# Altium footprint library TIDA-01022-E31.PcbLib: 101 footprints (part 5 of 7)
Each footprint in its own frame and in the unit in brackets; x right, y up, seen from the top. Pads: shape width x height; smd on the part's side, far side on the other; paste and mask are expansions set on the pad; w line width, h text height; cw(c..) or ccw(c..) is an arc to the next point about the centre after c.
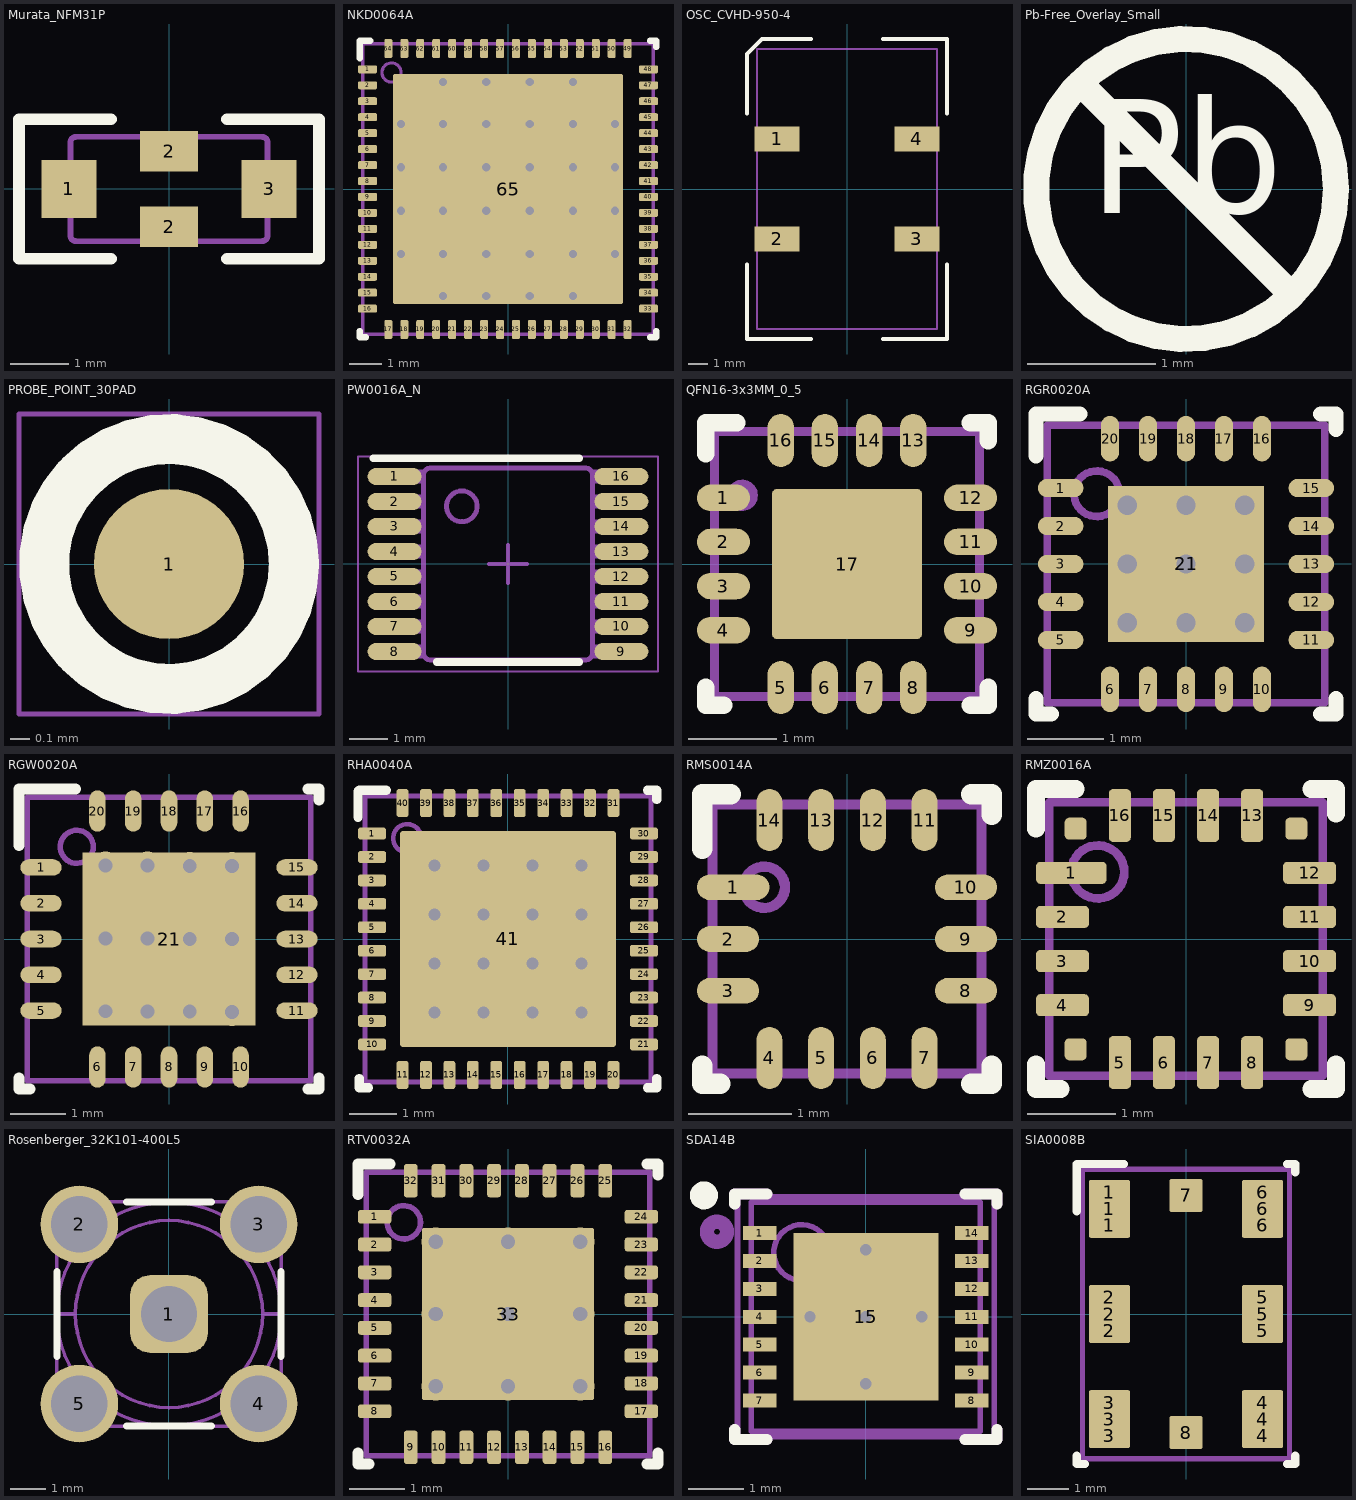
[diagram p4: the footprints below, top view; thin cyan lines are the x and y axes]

## Murata_NFM31P [mm] "SMD, 3-Leads, Body 3.2x1.6mm"
height 1.5
pads (4):
  rect 0.95x1 smd paste-2 mask-2: 1(-1.725,0) 3(1.725,0)
  rect 1x0.7 smd paste-2 mask+0: 2(0,-0.65) 2(0,0.65)
Top Overlay:
  lines w0.2: -1,-1.2 -2.586,-1.2 -2.586,1.2 -1,1.2 ; 1,-1.2 2.586,-1.2 2.586,1.2 1,1.2
Top Paste:
  rectangle: -0.5,0.3 0.5,1.3
  region: 0.5,-0.3 -0.5,-0.3 -0.5,-1.3 0.5,-1.3
  rectangle: 1.251,-0.6 2.201,0.6
  region: -1.251,0.6 -2.201,0.6 -2.201,-0.6 -1.251,-0.6
Top Solder:
  region: -0.7,1 -2.2,1 -2.2,-1 -0.7,-1
  rectangle: 0.7,-1 2.2,1
Mechanical 5:
  lines w0.1: -1.7,-0.8 ccw(c-1.6,-0.8) -1.6,-0.9 1.6,-0.9 ccw(c1.6,-0.8) 1.7,-0.8 1.7,0.8 ccw(c1.6,0.8) 1.6,0.9 -1.6,0.9 ccw(c-1.6,0.8) -1.7,0.8 -1.7,-0.8
  text ".Designator" at -0.117,-0.322 h0.51
3D body "NFM31PC276B0J3L.stp": height 1.5, standoff 0, extent -1.7,-0.9 1.7,0.9

## NKD0064A [mm] "QFN, 64-Leads, Body 9x9mm, Pitch 0.5mm"
height 0.8
pads (65):
  rrect40% 0.6x0.25 smd: 1(-4.4,3.75) 2(-4.4,3.25) 3(-4.4,2.75) 4(-4.4,2.25) 5(-4.4,1.75) 6(-4.4,1.25) 7(-4.4,0.75) 8(-4.4,0.25) 9(-4.4,-0.25) 10(-4.4,-0.75) 11(-4.4,-1.25) 12(-4.4,-1.75) 13(-4.4,-2.25) 14(-4.4,-2.75) 15(-4.4,-3.25) 16(-4.4,-3.75) 33(4.4,-3.75) 34(4.4,-3.25) 35(4.4,-2.75) 36(4.4,-2.25) 37(4.4,-1.75) 38(4.4,-1.25) 39(4.4,-0.75) 40(4.4,-0.25) 41(4.4,0.25) 42(4.4,0.75) 43(4.4,1.25) 44(4.4,1.75) 45(4.4,2.25) 46(4.4,2.75) 47(4.4,3.25) 48(4.4,3.75)
  rrect40% 0.25x0.6 smd: 17(-3.75,-4.4) 18(-3.25,-4.4) 19(-2.75,-4.4) 20(-2.25,-4.4) 21(-1.75,-4.4) 22(-1.25,-4.4) 23(-0.75,-4.4) 24(-0.25,-4.4) 25(0.25,-4.4) 26(0.75,-4.4) 27(1.25,-4.4) 28(1.75,-4.4) 29(2.25,-4.4) 30(2.75,-4.4) 31(3.25,-4.4) 32(3.75,-4.4) 49(3.75,4.4) 50(3.25,4.4) 51(2.75,4.4) 52(2.25,4.4) 53(1.75,4.4) 54(1.25,4.4) 55(0.75,4.4) 56(0.25,4.4) 57(-0.25,4.4) 58(-0.75,4.4) 59(-1.25,4.4) 60(-1.75,4.4) 61(-2.25,4.4) 62(-2.75,4.4) 63(-3.25,4.4) 64(-3.75,4.4)
  rrect1% 7.2x7.2 smd paste-3.6: 65(0,0)
via 0.68,0.68 diameter 0.508 hole 0.254
via -0.68,0.68 diameter 0.508 hole 0.254
via -0.68,-0.68 diameter 0.508 hole 0.254
via 0.68,-0.68 diameter 0.508 hole 0.254
via -2.04,0.68 diameter 0.508 hole 0.254
via 2.04,0.68 diameter 0.508 hole 0.254
via 2.04,-0.68 diameter 0.508 hole 0.254
via -2.04,-0.68 diameter 0.508 hole 0.254
via -2.04,-2.04 diameter 0.508 hole 0.254
via -0.68,-2.04 diameter 0.508 hole 0.254
via 0.68,-2.04 diameter 0.508 hole 0.254
via 2.04,-2.04 diameter 0.508 hole 0.254
via -2.04,2.04 diameter 0.508 hole 0.254
via -0.68,2.04 diameter 0.508 hole 0.254
via 0.68,2.04 diameter 0.508 hole 0.254
via 2.04,2.04 diameter 0.508 hole 0.254
via -2.04,3.35 diameter 0.508 hole 0.254
via -0.68,3.35 diameter 0.508 hole 0.254
via 0.68,3.35 diameter 0.508 hole 0.254
via 2.04,3.35 diameter 0.508 hole 0.254
via 0.68,-3.35 diameter 0.508 hole 0.254
via 2.04,-3.35 diameter 0.508 hole 0.254
via -0.68,-3.35 diameter 0.508 hole 0.254
via -2.04,-3.35 diameter 0.508 hole 0.254
via 3.35,-0.68 diameter 0.508 hole 0.254
via 3.35,-2.04 diameter 0.508 hole 0.254
via -3.35,-2.04 diameter 0.508 hole 0.254
via -3.35,-0.68 diameter 0.508 hole 0.254
via -3.35,2.04 diameter 0.508 hole 0.254
via -3.35,0.68 diameter 0.508 hole 0.254
via 3.35,2.04 diameter 0.508 hole 0.254
via 3.35,0.68 diameter 0.508 hole 0.254
Top Overlay:
  lines w0.2: -4.65,-4.45 -4.65,-4.65 -4.45,-4.65 ; -4.65,4.1 -4.65,4.65 -4.32,4.65 ; 4.45,-4.65 4.65,-4.65 4.65,-4.45 ; 4.45,4.65 4.65,4.65 4.65,4.45
Top Paste:
  rectangle: -0.58,-0.58 0.58,0.58
  rectangle: 0.78,-0.58 1.94,0.58
  rectangle: 2.14,-0.58 3.3,0.58
  rectangle: 0.78,0.78 1.94,1.94
  rectangle: 0.78,2.14 1.94,3.3
  rectangle: 2.14,2.14 3.3,3.3
  rectangle: 2.14,0.78 3.3,1.94
  rectangle: -0.58,0.78 0.58,1.94
  rectangle: -0.58,2.14 0.58,3.3
  rectangle: -1.94,2.14 -0.78,3.3
  rectangle: -3.3,2.14 -2.14,3.3
  rectangle: -3.3,0.78 -2.14,1.94
  rectangle: -1.94,0.78 -0.78,1.94
  rectangle: -1.94,-0.58 -0.78,0.58
  rectangle: -3.3,-0.58 -2.14,0.58
  rectangle: -3.3,-1.94 -2.14,-0.78
  rectangle: -1.94,-1.94 -0.78,-0.78
  rectangle: -0.58,-1.94 0.58,-0.78
  rectangle: 0.78,-1.94 1.94,-0.78
  rectangle: 2.14,-1.94 3.3,-0.78
  rectangle: 2.14,-3.3 3.3,-2.14
  rectangle: 0.78,-3.3 1.94,-2.14
  rectangle: -0.58,-3.3 0.58,-2.14
  rectangle: -1.94,-3.3 -0.78,-2.14
  rectangle: -3.3,-3.3 -2.14,-2.14
Mechanical 5:
  circle w0.1: c-3.65,3.65 r0.3
  lines w0.1: -4.55,-4.55 -4.55,4.55 4.55,4.55 4.55,-4.55 -4.55,-4.55
  text ".Designator" at -0.047,0.001 h0.51
3D body: height 0.8, standoff 0, extent -4.549,-4.549 4.549,4.549
3D body: height 0.81, standoff 0.5, extent -3.949,3.351 -3.351,3.949

## OSC_CVHD-950-4 [mil] "Crystek recommended land pattern 2011-02-22 Rev H"
height 210
pads (4):
  rect 90x50 smd: 1(-140,100) 2(-140,-100) 3(140,-100) 4(140,100)
Top Overlay:
  lines w7.87: -200,-151.18 -200,-300 -71.73,-300 ; -200,151.18 -200,270 -170,300 -71.73,300 ; 71.73,-300 200,-300 200,-151.18 ; 71.73,300 200,300 200,151.18
Mechanical 5:
  lines w4: -180,-280 180,-280 180,280 -180,280 -180,-280
  text ".Designator" at 18.56,-12.02 h20
3D body "Crystek_CVHD-950.stp": height 209.06, standoff -0.39, extent -179.84,-279.53 180,279.53

## Pb-Free_Overlay_Small [mm]
height 9.53
Top Overlay:
  circle w0.203: c0,0 r1.168
  lines w0.203: -0.826,0.826 0.826,-0.826
  text "Pb" at -0.752,-0.48 h1.52

## PROBE_POINT_30PAD [mil]
height 59.06
pads (1):
  round 30 smd: 1(0,0)
Top Overlay:
  circle w10: c0,0 r25
Mechanical 16:
  circle w1: c0,0 r25
  circle w1: c0,0 r29.15
  lines w1: -30,-30 30,-30 30,30 -30,30 -30,-30
Mechanical 30:
  text "1" at -10,-10 h25
Mechanical 31:
  text ".Designator" at -179.07,-26.87 h50

## PW0016A_N [mm] "TSOP, 16-Leads, Body 5x4.4mm, Pitch 0.65mm, IPC Medium Density"
height 1.2
pads (16):
  oval 1.4x0.45 smd: 1(-2.95,2.275) 2(-2.95,1.625) 3(-2.95,0.975) 4(-2.95,0.325) 5(-2.95,-0.325) 6(-2.95,-0.975) 7(-2.95,-1.625) 8(-2.95,-2.275) 9(2.95,-2.275) 10(2.95,-1.625) 11(2.95,-0.975) 12(2.95,-0.325) 13(2.95,0.325) 14(2.95,0.975) 15(2.95,1.625) 16(2.95,2.275)
Top Overlay:
  lines w0.2: -3.5,2.75 1.85,2.75 ; -1.85,-2.55 1.85,-2.55
Mechanical 5:
  drawing of 202 lines, arcs and shapes, not listed
  text ".Designator" at 0.859,0.328 h0.51
Mechanical 15:
  lines w0.05: -3.9,-2.8 -3.9,2.8 3.9,2.8 3.9,-2.8 -3.9,-2.8
  lines w0.1: -0.5,0 0.5,0 ; 0,-0.5 0,0.5
3D body "PW0016A.stp": height 1, standoff 0, extent -3.21,-2.5 3.21,2.5

## QFN16-3x3MM_0_5 [mm] "QFN, 16-Leads, Body 3x3mm, Pitch 0.5mm"
height 1
pads (17):
  rrect100% 0.6x0.3 smd: 1(-1.4,0.75) 2(-1.4,0.25) 3(-1.4,-0.25) 4(-1.4,-0.75) 9(1.4,-0.75) 10(1.4,-0.25) 11(1.4,0.25) 12(1.4,0.75)
  rrect100% 0.3x0.6 smd: 5(-0.75,-1.4) 6(-0.25,-1.4) 7(0.25,-1.4) 8(0.75,-1.4) 13(0.75,1.4) 14(0.25,1.4) 15(-0.25,1.4) 16(-0.75,1.4)
  rrect6% 1.7x1.7 smd paste-2: 17(0,0)
Top Overlay:
  lines w0.2: -1.6,-1.4 -1.6,-1.6 -1.4,-1.6 ; -1.6,1.25 -1.6,1.6 -1.25,1.6 ; 1.4,-1.6 1.6,-1.6 1.6,-1.4 ; 1.4,1.6 1.6,1.6 1.6,1.4
Top Paste:
  rectangle: -0.775,-0.774 0.774,0.775
Mechanical 5:
  circle w0.1: c-1.187,0.779 r0.127
  lines w0.1: -1.5,-1.5 1.5,-1.5 1.5,1.5 -1.5,1.5 -1.5,-1.5
3D body: height 1, standoff 0, extent -1.5,-1.5 1.5,1.5
3D body: height 1.01, standoff 1, extent -1.099,0.501 -0.501,1.099

## RGR0020A [mm] "QFN, 20-Leads, Body 3.5x3.5mm, Pitch 0.5mm, Thermal Pad 2.05x2.05mm, TI Recommended"
height 1
pads (21):
  oval 0.6x0.24 smd: 1(-1.65,1) 2(-1.65,0.5) 3(-1.65,0) 4(-1.65,-0.5) 5(-1.65,-1) 11(1.65,-1) 12(1.65,-0.5) 13(1.65,0) 14(1.65,0.5) 15(1.65,1)
  oval 0.24x0.6 smd: 6(-1,-1.65) 7(-0.5,-1.65) 8(0,-1.65) 9(0.5,-1.65) 10(1,-1.65) 16(1,1.65) 17(0.5,1.65) 18(0,1.65) 19(-0.5,1.65) 20(-1,1.65)
  rect 2.05x2.05 smd paste-1.025: 21(0,0)
via 0.775,0 diameter 0.508 hole 0.254
via -0.775,0 diameter 0.508 hole 0.254
via 0,0.775 diameter 0.508 hole 0.254
via 0,-0.775 diameter 0.508 hole 0.254
via 0,0 diameter 0.508 hole 0.254
via 0.775,0.775 diameter 0.508 hole 0.254
via 0.775,-0.775 diameter 0.508 hole 0.254
via -0.775,-0.775 diameter 0.508 hole 0.254
via -0.775,0.775 diameter 0.508 hole 0.254
Top Overlay:
  lines w0.2: -1.975,-1.775 -1.975,-1.975 -1.775,-1.975 ; -1.975,1.425 -1.975,1.975 -1.4,1.975 ; 1.775,-1.975 1.975,-1.975 1.975,-1.775 ; 1.775,1.975 1.975,1.975 1.975,1.775
Top Paste:
  rectangle: 0.099,-1.017 1.016,-0.1
  region: -0.099,-0.1 -1.016,-0.1 -1.016,-1.017 -0.099,-1.017
  region: -0.099,1.017 -1.016,1.017 -1.016,0.1 -0.099,0.1
  rectangle: 0.101,0.1 1.018,1.017
Mechanical 5:
  circle w0.1: c-1.175,0.925 r0.3
  lines w0.1: -1.825,-1.825 1.825,-1.825 1.825,1.825 -1.825,1.825 -1.825,-1.825
  text ".Designator" at -0.052,0.631 h0.51
3D body: height 1, standoff 0, extent -1.825,-1.825 1.825,1.825
3D body: height 1.01, standoff 0.5, extent -1.474,0.626 -0.876,1.224

## RGW0020A [mm] "QFN, 20-Leads, Body 5x5mm, Pitch 0.65mm, Thermal Pad 3.15x3.15mm, TI Recommended"
height 1
pads (21):
  oval 0.75x0.3 smd: 1(-2.325,1.3) 2(-2.325,0.65) 3(-2.325,0) 4(-2.325,-0.65) 5(-2.325,-1.3) 11(2.325,-1.3) 12(2.325,-0.65) 13(2.325,0) 14(2.325,0.65) 15(2.325,1.3)
  oval 0.3x0.75 smd: 6(-1.3,-2.325) 7(-0.65,-2.325) 8(0,-2.325) 9(0.65,-2.325) 10(1.3,-2.325) 16(1.3,2.325) 17(0.65,2.325) 18(0,2.325) 19(-0.65,2.325) 20(-1.3,2.325)
  rect 3.15x3.15 smd paste-1.575: 21(0,0)
via -0.389,-1.317 diameter 0.508 hole 0.254
via -0.389,0.008 diameter 0.508 hole 0.254
via -1.156,0.013 diameter 0.508 hole 0.254
via -0.389,1.333 diameter 0.508 hole 0.254
via -1.156,1.338 diameter 0.508 hole 0.254
via -1.156,-1.312 diameter 0.508 hole 0.254
via 0.377,1.329 diameter 0.508 hole 0.254
via 0.377,0.004 diameter 0.508 hole 0.254
via 0.377,-1.321 diameter 0.508 hole 0.254
via 1.143,1.325 diameter 0.508 hole 0.254
via 1.143,0 diameter 0.508 hole 0.254
via 1.143,-1.325 diameter 0.508 hole 0.254
Top Overlay:
  lines w0.2: -2.725,-2.525 -2.725,-2.725 -2.525,-2.725 ; -2.725,1.7 -2.725,2.725 -1.7,2.725 ; 2.525,-2.725 2.725,-2.725 2.725,-2.525 ; 2.525,2.725 2.725,2.725 2.725,2.525
Top Paste:
  rectangle: 0.1,-1.468 1.468,-0.1
  region: -0.1,-0.1 -1.468,-0.1 -1.468,-1.468 -0.1,-1.468
  region: -0.1,1.468 -1.468,1.468 -1.468,0.1 -0.1,0.1
  rectangle: 0.1,0.1 1.468,1.468
Mechanical 5:
  circle w0.1: c-1.675,1.675 r0.3
  lines w0.1: -2.575,-2.575 2.575,-2.575 2.575,2.575 -2.575,2.575 -2.575,-2.575
  text ".Designator" at -0.658,-0.13 h0.51
3D body: height 1.01, standoff 0.5, extent -1.974,1.376 -1.376,1.974
3D body: height 1, standoff 0, extent -2.575,-2.575 2.575,2.575

## RHA0040A [mm] "QFN, 40-Leads, Body 6x6mm, Pitch 0.5mm, Thermal Pad 4.6x4.6mm, TI Recommended"
height 1
pads (41):
  rrect40% 0.6x0.25 smd: 1(-2.9,2.25) 2(-2.9,1.75) 3(-2.9,1.25) 4(-2.9,0.75) 5(-2.9,0.25) 6(-2.9,-0.25) 7(-2.9,-0.75) 8(-2.9,-1.25) 9(-2.9,-1.75) 10(-2.9,-2.25) 21(2.9,-2.25) 22(2.9,-1.75) 23(2.9,-1.25) 24(2.9,-0.75) 25(2.9,-0.25) 26(2.9,0.25) 27(2.9,0.75) 28(2.9,1.25) 29(2.9,1.75) 30(2.9,2.25)
  rrect40% 0.25x0.6 smd: 11(-2.25,-2.9) 12(-1.75,-2.9) 13(-1.25,-2.9) 14(-0.75,-2.9) 15(-0.25,-2.9) 16(0.25,-2.9) 17(0.75,-2.9) 18(1.25,-2.9) 19(1.75,-2.9) 20(2.25,-2.9) 31(2.25,2.9) 32(1.75,2.9) 33(1.25,2.9) 34(0.75,2.9) 35(0.25,2.9) 36(-0.25,2.9) 37(-0.75,2.9) 38(-1.25,2.9) 39(-1.75,2.9) 40(-2.25,2.9)
  rrect2% 4.6x4.6 smd paste-2.3: 41(0,0)
via 1.57,-1.57 diameter 0.508 hole 0.254
via 1.57,-0.523 diameter 0.508 hole 0.254
via 1.57,1.57 diameter 0.508 hole 0.254
via 1.57,0.523 diameter 0.508 hole 0.254
via -1.57,-1.57 diameter 0.508 hole 0.254
via -1.57,-0.523 diameter 0.508 hole 0.254
via -1.57,1.57 diameter 0.508 hole 0.254
via -1.57,0.523 diameter 0.508 hole 0.254
via -0.523,0.523 diameter 0.508 hole 0.254
via 0.523,-1.57 diameter 0.508 hole 0.254
via 0.523,0.523 diameter 0.508 hole 0.254
via 0.523,1.57 diameter 0.508 hole 0.254
via -0.523,1.57 diameter 0.508 hole 0.254
via -0.523,-0.523 diameter 0.508 hole 0.254
via -0.523,-1.57 diameter 0.508 hole 0.254
via 0.523,-0.523 diameter 0.508 hole 0.254
Top Overlay:
  lines w0.2: -3.2,2.6 -3.2,3.15 ; -3.175,-2.975 -3.175,-3.175 -2.975,-3.175 ; -3.175,3.175 -2.6,3.175 ; 2.975,-3.175 3.175,-3.175 3.175,-2.975 ; 2.975,3.175 3.175,3.175 3.175,2.975
Top Paste:
  region: -0.84,-0.84 -2.12,-0.84 -2.12,-2.12 -0.84,-2.12
  rectangle: 0.84,-2.12 2.12,-0.84
  rectangle: -0.64,-2.12 0.64,-0.84
  rectangle: -0.64,0.84 0.64,2.12
  rectangle: 0.84,0.84 2.12,2.12
  region: -0.84,2.12 -2.12,2.12 -2.12,0.84 -0.84,0.84
  region: -0.84,0.64 -2.12,0.64 -2.12,-0.64 -0.84,-0.64
  rectangle: 0.84,-0.64 2.12,0.64
  rectangle: -0.64,-0.64 0.64,0.64
Mechanical 5:
  circle w0.1: c-2.15,2.15 r0.3
  lines w0.1: -3.05,-3.05 -3.05,3.05 3.05,3.05 3.05,-3.05 -3.05,-3.05
  text ".Designator" at 0.457,-0.576 h0.51
3D body "RHA0040A.stp": height 1, standoff 0, extent -3,-3 3,3

## RMS0014A [mm] "QFN, Body 2.6x2.6mm, Pitch 0.5mm"
height 0.6
pads (14):
  oval 0.7x0.25 smd: 1(-1.1,0.5)
  oval 0.6x0.25 smd: 2(-1.15,0) 3(-1.15,-0.5) 8(1.15,-0.5) 9(1.15,0) 10(1.15,0.5)
  oval 0.25x0.6 smd: 4(-0.75,-1.15) 5(-0.25,-1.15) 6(0.25,-1.15) 7(0.75,-1.15) 11(0.75,1.15) 12(0.25,1.15) 13(-0.25,1.15) 14(-0.75,1.15)
Top Overlay:
  lines w0.2: -1.4,-1.225 -1.4,-1.4 -1.225,-1.4 ; -1.4,0.875 -1.4,1.4 -1.125,1.4 ; 1.2,-1.4 1.4,-1.4 1.4,-1.225 ; 1.2,1.4 1.4,1.4 1.4,1.2
Mechanical 5:
  circle w0.1: c-0.8,0.5 r0.2
  lines w0.1: -1.3,-1.3 1.3,-1.3 1.3,1.3 -1.3,1.3 -1.3,-1.3
  text ".Designator" at 0.51,-0.374 h0.51
3D body: height 0.6, standoff 0, extent -1.299,-1.299 1.299,1.299
3D body: height 0.61, standoff 0, extent -0.999,0.301 -0.601,0.699

## RMZ0016A [mm] "QFN, 16-Leads, Body 3.0x3.0 mm, Pitch 0.5mm"
height 0.65
pads (20):
  rrect40% 0.8x0.25 smd paste+0 mask+0.07: 1(-1.3,0.75)
  rrect40% 0.6x0.25 smd paste+0 mask+0.07: 2(-1.4,0.25) 3(-1.4,-0.25) 4(-1.4,-0.75) 9(1.4,-0.75) 10(1.4,-0.25) 11(1.4,0.25) 12(1.4,0.75)
  rrect40% 0.25x0.6 smd paste+0 mask+0.07: 5(-0.75,-1.4) 6(-0.25,-1.4) 7(0.25,-1.4) 8(0.75,-1.4) 13(0.75,1.4) 14(0.25,1.4) 15(-0.25,1.4) 16(-0.75,1.4)
  rrect40% 0.25x0.25 smd paste+0 mask+0.07: ""(-1.25,-1.25) ""(-1.25,1.25) ""(1.25,-1.25) ""(1.25,1.25)
Top Overlay:
  lines w0.2: -1.7,-1.42 -1.7,-1.7 -1.42,-1.7 ; -1.7,1.25 -1.7,1.7 -1.25,1.7 ; 1.42,-1.7 1.7,-1.7 1.7,-1.42 ; 1.42,1.7 1.7,1.7 1.7,1.42
Mechanical 5:
  circle w0.1: c-1,0.76 r0.3
  lines w0.1: -1.55,-1.55 1.55,-1.55 1.55,1.55 -1.55,1.55 -1.55,-1.55
  text ".Designator" at -0.302,-0.491 h0.51
3D body: height 0.65, standoff 0, extent -1.55,-1.55 1.55,1.55
3D body: height 0.66, standoff 0.5, extent -1.299,0.461 -0.701,1.059

## Rosenberger_32K101-400L5 [mm] "SMA, 50 Ohm, TH"
height 9.5
pads (5):
  rrect50% 2.2x2.2 hole 1.6: 1(0,0)
  round 2.2 hole 1.6: 2(-2.54,2.54) 3(2.54,2.54) 4(2.54,-2.54) 5(-2.54,-2.54)
Top Overlay:
  lines w0.2: -3.175,-1.2 -3.175,1.2 ; -1.2,-3.175 1.2,-3.175 ; -1.2,3.175 1.2,3.175 ; 3.175,-1.2 3.175,1.2
Mechanical 5:
  lines w0.1: -3.175,0 ccw(c0,0) 3.175,0 ; -3.175,0 cw(c0,0) 3.175,0 ; -3.175,0 -2.65,0 ; -2.65,0 ccw(c0,0) 2.65,0 ; -2.65,0 cw(c0,0) 2.65,0 ; 2.65,0 3.175,0 ; -3.175,-2.825 ccw(c0,0) -2.825,-3.175 2.825,-3.175 ccw(c0,0) 3.175,-2.825 3.175,2.825 ccw(c0,0) 2.825,3.175 -2.825,3.175 ccw(c0,0) -3.175,2.825 -3.175,-2.825
  text ".Designator" at 0.221,-0.611 h0.51
3D body "32k101-400l5.stp": height 9.51, standoff -3.99, extent -3.175,-3.175 3.175,3.175

## RTV0032A [mm] "QFN, 32-Leads, Body 5x5mm, Pitch 0.5mm"
height 0.8
pads (33):
  rrect40% 0.6x0.25 smd: 1(-2.4,1.75) 2(-2.4,1.25) 3(-2.4,0.75) 4(-2.4,0.25) 5(-2.4,-0.25) 6(-2.4,-0.75) 7(-2.4,-1.25) 8(-2.4,-1.75) 17(2.4,-1.75) 18(2.4,-1.25) 19(2.4,-0.75) 20(2.4,-0.25) 21(2.4,0.25) 22(2.4,0.75) 23(2.4,1.25) 24(2.4,1.75)
  rrect40% 0.25x0.6 smd: 9(-1.75,-2.4) 10(-1.25,-2.4) 11(-0.75,-2.4) 12(-0.25,-2.4) 13(0.25,-2.4) 14(0.75,-2.4) 15(1.25,-2.4) 16(1.75,-2.4) 25(1.75,2.4) 26(1.25,2.4) 27(0.75,2.4) 28(0.25,2.4) 29(-0.25,2.4) 30(-0.75,2.4) 31(-1.25,2.4) 32(-1.75,2.4)
  rrect3% 3.1x3.1 smd paste-1.55: 33(0,0)
via 1.3,-1.3 diameter 0.508 hole 0.254
via 1.3,1.3 diameter 0.508 hole 0.254
via -1.3,1.3 diameter 0.508 hole 0.254
via -1.3,-1.3 diameter 0.508 hole 0.254
via 0,-1.3 diameter 0.508 hole 0.254
via 1.3,0 diameter 0.508 hole 0.254
via 0,0 diameter 0.508 hole 0.254
via -1.3,0 diameter 0.508 hole 0.254
via 0,1.3 diameter 0.508 hole 0.254
Top Overlay:
  lines w0.2: -2.7,-2.5 -2.7,-2.7 -2.5,-2.7 ; -2.7,2.15 -2.7,2.7 -2.125,2.7 ; 2.5,-2.7 2.7,-2.7 2.7,-2.5 ; 2.5,2.7 2.7,2.7 2.7,2.5
Top Paste:
  rectangle: 0.1,-1.4 1.4,-0.1
  region: -0.1,-0.1 -1.4,-0.1 -1.4,-1.4 -0.1,-1.4
  region: -0.1,1.4 -1.4,1.4 -1.4,0.1 -0.1,0.1
  rectangle: 0.1,0.1 1.4,1.4
Mechanical 5:
  circle w0.1: c-1.875,1.65 r0.3
  lines w0.1: -2.55,-2.55 2.55,-2.55 2.55,2.55 -2.55,2.55 -2.55,-2.55
  text ".Designator" at -0.814,-0.185 h0.51
3D body: height 0.81, standoff 0.5, extent -2.174,1.351 -1.576,1.949
3D body: height 0.8, standoff 0, extent -2.55,-2.55 2.55,2.55

## SDA14B [mm] "SON, 14-Leads, Body 4x4mm, Pitch 0.5mm, NSC Recommended"
height 0.8
pads (15):
  rect 0.6x0.25 smd paste-0.125 mask+0.051: 1(-1.9,1.5) 2(-1.9,1) 3(-1.9,0.5) 4(-1.9,0) 5(-1.9,-0.5) 6(-1.9,-1) 7(-1.9,-1.5) 8(1.9,-1.5) 9(1.9,-1) 10(1.9,-0.5) 11(1.9,0) 12(1.9,0.5) 13(1.9,1) 14(1.9,1.5)
  rect 2.6x3 smd paste-1.3 mask+0.051: 15(0,0)
via 0,1.2 diameter 0.406 hole 0.203
via 0,-1.2 diameter 0.406 hole 0.203
via -1,0 diameter 0.406 hole 0.203
via 1,0 diameter 0.406 hole 0.203
via 0,0 diameter 0.406 hole 0.203
Top Overlay:
  circle w0.25: c-2.9,2.175 r0.125
  lines w0.2: -2.35,-2.025 -2.35,-2.2 -1.775,-2.2 ; -2.35,2.025 -2.35,2.2 -1.775,2.2 ; 1.775,-2.2 2.35,-2.2 2.35,-2.025 ; 1.775,2.2 2.35,2.2 2.35,2.025
Top Paste:
  region: -2.4,0.625 -2.4,0.375 -1.7,0.375 -1.7,0.625
  region: 1.7,-1.375 1.7,-1.625 2.4,-1.625 2.4,-1.375
  region: 1.7,-0.875 1.7,-1.125 2.4,-1.125 2.4,-0.875
  region: 1.7,-0.375 1.7,-0.625 2.4,-0.625 2.4,-0.375
  region: 1.7,0.125 1.7,-0.125 2.4,-0.125 2.4,0.125
  region: 1.7,0.625 1.7,0.375 2.4,0.375 2.4,0.625
  region: 1.7,1.125 1.7,0.875 2.4,0.875 2.4,1.125
  region: 1.7,1.625 1.7,1.375 2.4,1.375 2.4,1.625
  region: -2.4,1.625 -2.4,1.375 -1.7,1.375 -1.7,1.625
  region: -2.4,1.125 -2.4,0.875 -1.7,0.875 -1.7,1.125
  region: -2.4,0.125 -2.4,-0.125 -1.7,-0.125 -1.7,0.125
  region: -2.4,-0.375 -2.4,-0.625 -1.7,-0.625 -1.7,-0.375
  region: -2.4,-0.875 -2.4,-1.125 -1.7,-1.125 -1.7,-0.875
  region: -2.4,-1.375 -2.4,-1.625 -1.7,-1.625 -1.7,-1.375
  rectangle: -1.2,0.1 -0.1,1.4
  rectangle: -1.2,-1.4 -0.1,-0.1
  region: 1.2,-0.1 0.1,-0.1 0.1,-1.4 1.2,-1.4
  region: 1.2,1.4 0.1,1.4 0.1,0.1 1.2,0.1
Mechanical 5:
  circle w0.254: c-2.667,1.524 r0.18
  lines w0.2: -2.35,-2.025 -2.35,-2.2 -1.775,-2.2 ; -2.35,2.025 -2.35,2.2 -1.775,2.2 ; 1.775,-2.2 2.35,-2.2 2.35,-2.025 ; 1.775,2.2 2.35,2.2 2.35,2.025
  text ".Designator" at -0.512,-0.039 h0.51
Mechanical 13:
  circle w0.1: c-1.15,1.15 r0.5
  lines w0.1: -2.05,-2.05 2.05,-2.05 2.05,2.05 -2.05,2.05 -2.05,-2.05
Mechanical 15:
  lines w0.1: -0.5,0 0.5,0 ; 0,-0.5 0,0.5 ; -2.3,-2.15 2.3,-2.15 2.3,2.15 -2.3,2.15 -2.3,-2.15
3D body: height 0.8, standoff 0, extent -2.049,-2.049 2.049,2.049

## SIA0008B [mm] "SIP 8-Leads, Body 5x7mm"
height 1.1
pads (20):
  rrect50% 1x0.6 on Top Paste: 1(-1.85,2.14) 1(-1.85,2.94) 2(-1.85,-0.4) 2(-1.85,0.4) 3(-1.85,-2.94) 3(-1.85,-2.14) 4(1.85,-2.94) 4(1.85,-2.14) 5(1.85,-0.4) 5(1.85,0.4) 6(1.85,2.14) 6(1.85,2.94)
  rrect10% 1x1.4 smd paste-0.5: 1(-1.85,2.54) 2(-1.85,0) 3(-1.85,-2.54) 4(1.85,-2.54) 5(1.85,0) 6(1.85,2.54)
  rrect12% 0.8x0.8 smd: 7(0,2.865) 8(0,-2.865)
Top Overlay:
  lines w0.2: -2.64,-3.425 -2.64,-3.625 -2.44,-3.625 ; -2.64,2.485 -2.64,3.625 -1.5,3.625 ; 2.44,-3.625 2.64,-3.625 2.64,-3.425 ; 2.44,3.625 2.64,3.625 2.64,3.425
Mechanical 5:
  circle w0.1: c-1.84,2.54 r0.25
  lines w0.127: -2.5,-3.5 2.5,-3.5 2.5,3.5 -2.5,3.5 -2.5,-3.5
  text ".Designator" at -0.047,0.534 h0.51
3D body: height 1.1, standoff 0, extent -2.564,-3.564 2.564,3.564
3D body: height 1.13, standoff 0, extent -2.156,2.224 -1.525,2.856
